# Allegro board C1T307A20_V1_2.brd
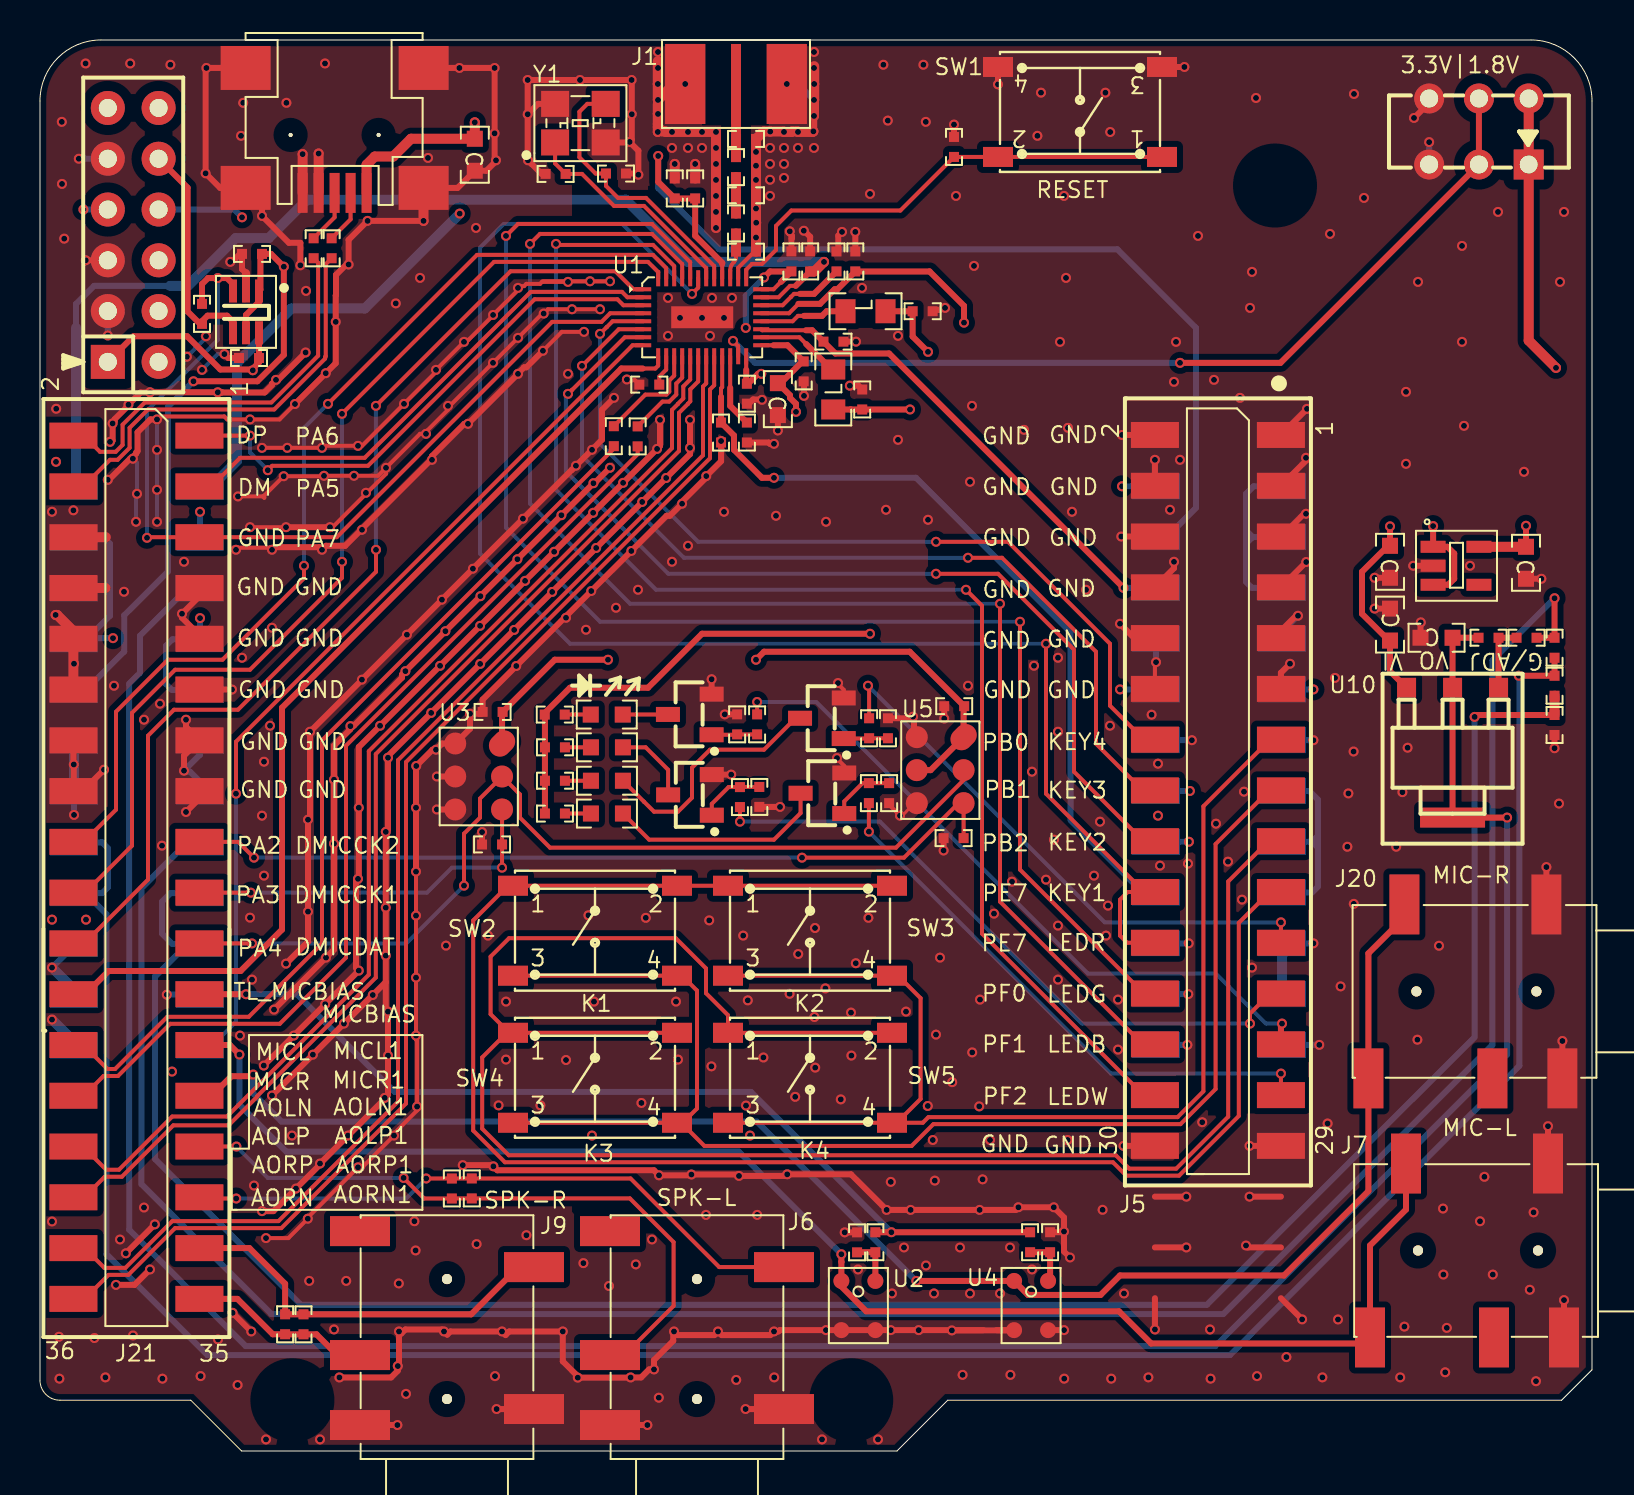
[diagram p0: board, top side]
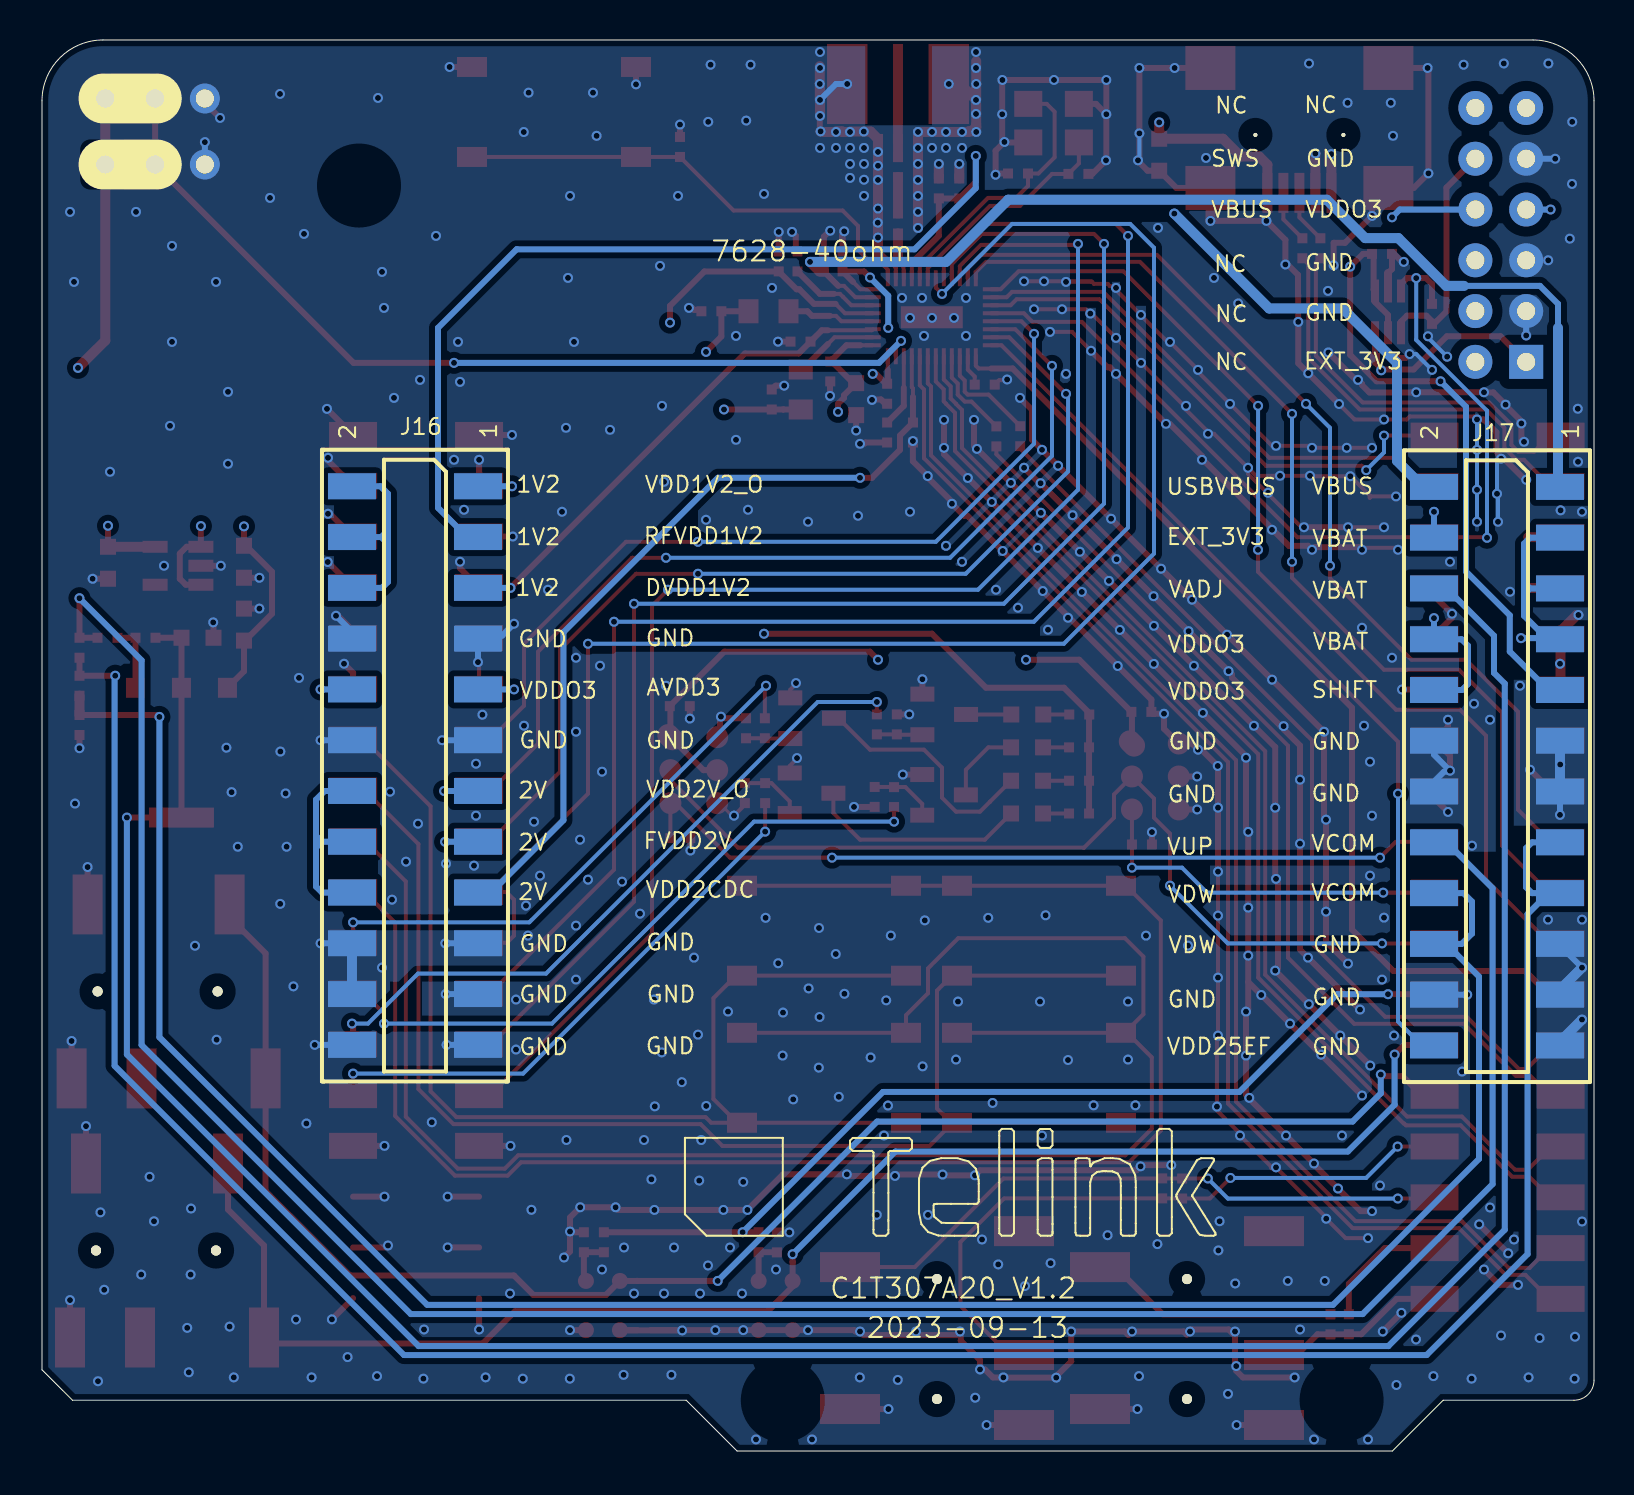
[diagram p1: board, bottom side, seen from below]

Outline 77.6 x 70.58 mm; copper layers: TOP, GND, POWER, BOTTOM. Coordinates in mm from the lower left corner of the outline.
Outline path: 0,67.53 arc(0.89,69.69) 3.05,70.58 74.55,70.58 arc(76.71,69.69) 77.6,67.53 77.6,4.06 76.08,2.54 45.39,2.54 42.85,0 10.08,0 7.54,2.54 1,2.54 arc(0.29,2.83) 0,3.54 0,67.53

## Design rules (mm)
constraint set DEFAULT: min track width 0.15

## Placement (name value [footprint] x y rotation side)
C1  NC  [0402]  28.8 63.9 180 top
C2  NC  [0402]  25.78 63.88 0 top
C3  0.1uF  [0402]  32.76 63.15 90 top
C4  2.2uF  [0402]  31.74 63.15 90 top
C5  NC  [0402]  35.3 59.99 180 top
C6  NC  [0402]  35.3 62.81 180 top
C9  1uF  [0402]  45.7 65.23 90 top
C10  1uF  [0402]  37.57 59.5 90 top
C11  1uF  [0402]  38.51 59.5 90 top
C12  1uF  [0402]  40.77 59.5 90 top
C13  1uF  [0402]  39.83 59.5 90 top
C14  1uF  [0402]  44.13 57.01 0 top
C15  1uF  [0402]  30.46 53.34 180 top
C16  1uF  [0402]  35.34 52.89 270 top
C17  1uF  [0402]  39.67 55.49 0 top
C18  1uF  [0402]  38.19 54 270 top
C19  1uF  [0402]  28.69 50.76 270 top
C20  1uF  [0402]  29.88 50.75 270 top
C21  1uF  [0402]  41.11 52.6 90 top
C22  1uF  [0402]  34.05 50.94 270 top
C23  1uF  [0402]  35.34 50.94 270 top
C25  NC  [0402]  21.59 13.13 90 top
C26  1uF  [0402]  40.85 10.44 90 top
C27  0.1uF  [0402]  45.71 37.26 180 top
C28  NC  [0402]  13.17 6.34 90 top
C29  1uF  [0402]  50.5 10.44 90 top
C30  10uF  [0603C]  21.74 64.84 270 top
C31  0.1uF  [0402]  22.63 36.97 180 top
C33  0.1uF  [0402]  10.6 59.88 180 top
C34  0.1uF  [0402]  10.45 54.67 180 top
C37  10uF  [0603C]  67.5 41.34 90 top
C38  10uF  [0603C]  67.5 44.48 270 top
C39  10uF  [0603C]  74.3 44.43 270 top
C40  10uF  [0603C]  69.83 40.68 180 top
C43  10uF  [0603C]  36.89 52.61 270 top
C44  NC  [0402]  35.3 65.63 180 top
D1  Blue  [0603-LED]  28.34 36.84 0 top
D2  Green  [0603-LED]  28.35 35.2 0 top
D3  White  [0603-LED]  28.35 31.89 0 top
D4  Red  [0603-LED]  28.35 33.53 0 top
J1  RFIN  [SMA-H]  34.8 68.38 270 top
J5  HEADER 15X2  [SMD254M-2X15_RX1_30Y2_40]  58.9 24.15 90 top
J6  AOPHR  [PJ-327]  32.85 -0.4 180 top
J7  AIL1  [PJ-327]  77.9 10.03 270 top
J9  AOPHR  [PJ-327]  20.35 -0.4 180 top
J11  USB_MiniABF  [USB-MINI-F5]  14.73 62.93 180 top
J15  JTAG  [HDR254F-2X6X850]  3.39 67.18 270 top
J16  HEADER 12X2  [SMD254M-2X12_RX1_30Y2_40]  58.95 34.29 90 bottom
J17  HEADER 12X2  [SMD254M-2X12_RX1_30Y2_40]  4.85 34.26 90 bottom
J20  AIL1  [PJ-327]  77.82 22.99 270 top
J21  HEADER 18X2  [SMD254M-2X18_RX1_30Y2_40]  4.82 24.12 90 top
L1  0R  [0402]  34.8 61.4 90 top
L2  2.2uH  [0805L]  41.28 57.01 0 top
L3  2.2uH  [0805L]  39.66 53.1 270 top
L4  0R  [0402]  34.8 64.22 90 top
Q2  C1815  [SOT-23]  39.09 36.65 90 top
Q3  C1815  [SOT-23]  32.49 36.84 90 top
Q4  C1815  [SOT-23]  39.12 32.9 90 top
Q5  C1815  [SOT-23]  32.5 32.82 90 top
R4  1K  [0402]  25.74 36.84 0 top
R5  1K  [0402]  25.75 35.2 0 top
R6  1K  [0402]  25.75 31.89 0 top
R7  1K  [0402]  25.75 33.53 0 top
R8  NC  [0402]  20.59 13.13 90 top
R9  2.2K  [0402]  41.77 10.44 270 top
R10  100K  [0402]  22.6 30.34 0 top
R11  NC  [0402]  12.26 6.34 90 top
R12  2.2K  [0402]  49.5 10.44 270 top
R13  100K  [0402]  45.68 30.66 0 top
R14  33  [0402R]  14.58 60.16 270 top
R15  33  [0402R]  13.68 60.16 270 top
R26  0R  [0402R]  8.1 56.88 270 top
R33  430R  [0402]  74.33 40.68 0 top
R34  1.15K  [0402]  75.73 40.18 270 top
R35  787R  [0402]  75.73 38.28 270 top
R36  464R  [0402]  75.73 36.32 270 top
R37  1K  [0402]  72.43 40.68 180 top
R39  1K  [0402]  35.86 36.35 270 top
R45  1K  [0402]  35 32.71 90 top
R46  1K  [0402]  41.44 32.91 90 top
R47  1K  [0402]  41.46 36.15 270 top
R48  1M  [0402]  34.86 36.35 90 top
R49  1M  [0402]  35.97 32.72 270 top
R50  1M  [0402]  42.46 32.91 270 top
R51  1M  [0402]  42.4 36.15 90 top
S1  SW_SL_DPDT  [SW-TH-6PIN-3_60X9_00-34NP]  71.95 66 0 top
SW1  SW4PIN_4.5x4.5  [SW_6X6_SMD]  52 66.98 180 top
SW2  SW4PIN_4.5x4.5  [SW_6X6_SMD]  27.75 26.03 0 top
SW3  SW4PIN_4.5x4.5  [SW_6X6_SMD]  38.5 26.03 0 top
SW4  SW4PIN_4.5x4.5  [SW_6X6_SMD]  27.75 18.67 0 top
SW5  SW4PIN_4.5x4.5  [SW_6X6_SMD]  38.5 18.67 0 top
U1  TLSR9527B  [QFN_4X6_40PIN_0P4_1P10X3P10]  33.11 56.71 0 top
U2  MWW7037AT2  [GA_BFA423_A83]  40.92 7.28 0 top
U3  SPM0423HM4H-WB  [DMIC_SPM0423HM4H-WB]  21.93 33.74 270 top
U4  MWW7037AT2  [GA_BFA423_A83]  49.55 7.28 0 top
U5  SPM0423HM4H-WB  [DMIC_SPM0423HM4H-WB]  45.01 34.06 270 top
U8  TXS0101  [SC70-6]  10.3 56.98 180 top
U10  LM1117-ADJ  [SOT-223]  70.63 34.68 180 top
U11  CE1132-33M  [SOT-23-5]  70.8 44.28 270 top
Y1  24MHz-12pF-+/-20ppm  [OSCCC250X320X110]  27.02 66.42 90 top

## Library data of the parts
C1 C2 = C1005_NC
C3 C4 C9-C23 C26 C27 C29 C31 C38 C39 = C1005X5R1C104K
C5 C6 C44 = C1608_NC
C25 C28 = C1005X5R1C105K
C30 C37 = C1608X5R0J106M
C33 C34 C40 = C1608X5R1C105M
C43 = C1005X5R1C104K_0
D1-D4 = 0603D_Green
J1 = SMA_JACK_2
J5 = HEADER 15X2: Tolerance: RichardLC
J6 J7 J9 J20 = PJ327_2
J11 = USB_MiniABF_5pin: User Part Number: pn; Tolerance: RichardLC
J15 = HEADER 6X2: User Part Number: pn; Tolerance: RichardLC
J16 J17 = HEADER 12X2: Tolerance: RichardLC
J21 = HEADER 18X2: Tolerance: RichardLC
L1 L4 = MLK1608_000R
L2 L3 = IND
Q2-Q5 = NPN_C1815
R4-R7 = RS0402K102JT
R8-R13 = RS0402K104JT
R14 R15 = RS0603K330JT
R26 = RS0603K102JT
R33-R37 = RS0603K104JT
R39 R45-R51 = RS0402K101JT
S1 = SW_SL_DPDT: User Part Number: pn; Tolerance: RichardLC
SW1-SW5 = SW_6X6_SMD_0
U1 = TLSR9527B
U2 U4 = MULPS4CX-RM5_0
U3 U5 = LD1117/SO_0
U8 = TXS0101
U10 = XC62FP3302_0.3V_SOT-89
U11 = XC6219_6.3V_SOT-23-5
Y1 = CRYSTAL4/SM_0: Tolerance: RichardLC

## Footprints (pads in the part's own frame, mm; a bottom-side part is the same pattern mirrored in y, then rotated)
0402
  rect 0.5x0.5 smd: 1(-0.5,0) 2(0.5,0)
0402R
  rect 0.5x0.5 smd: 1(-0.5,0) 2(0.5,0)
0603-LED
  rect 0.8x0.8 smd: A(-0.8,0) C(0.8,0)
0603C
  rect 0.8x0.8 smd: 1(-0.8,0) 2(0.8,0)
0805L
  rect 1x1.2 smd: 1(-1,0) 2(1,0)
DMIC_SPM0423HM4H-WB
  round 1.1 smd: 1(-1.65,-1.17) 2(0,-1.17) 3(1.65,-1.17) 4(1.65,1.17) 5(0,1.17)
  oval 1.4x1.1 smd rot 135: 6(-1.65,1.17)
GA_BFA423_A83
  round 0.8 smd: 1(-0.85,1.23) 2(-0.85,-1.23) 3(0.85,-1.23) 4(0.85,1.23)
HDR254F-2X6X850
  rect 1.7x1.7 hole 0.9: 1(12.7,0)
  round 1.7 hole 0.9: 2(12.7,2.54) 3(10.16,0) 4(10.16,2.54) 5(7.62,0) 6(7.62,2.54) 7(5.08,0) 8(5.08,2.54) 9(2.54,0) 10(2.54,2.54) 11(0,0) 12(0,2.54)
OSCCC250X320X110
  rect 1.3x1.4 smd: 1(-0.965,1.265) 2(-0.965,-1.265) 3(0.965,-1.265) 4(0.965,1.265)
PJ-327
  round 0.5 hole 1: (0,-3) (0,-9)
  rect 3x1.5 smd: 1(-4.35,-2.5) 2(4.35,-5.2) 3(-4.35,-9.6) 4(4.35,-11.4) 5(4.35,-1.7)
QFN_4X6_40PIN_0P4_1P10X3P10
  rect 0.8x0.2 smd: 1(-2.95,1.4) 2(-2.95,1) 3(-2.95,0.6) 4(-2.95,0.2) 5(-2.95,-0.2) 6(-2.95,-0.6) 7(-2.95,-1) 8(-2.95,-1.4) 21(2.95,-1.4) 22(2.95,-1) 23(2.95,-0.6) 24(2.95,-0.2) 25(2.95,0.2) 26(2.95,0.6) 27(2.95,1) 28(2.95,1.4)
  rect 0.2x0.8 smd: 9(-2.2,-1.95) 10(-1.8,-1.95) 11(-1.4,-1.95) 12(-1,-1.95) 13(-0.6,-1.95) 14(-0.2,-1.95) 15(0.2,-1.95) 16(0.6,-1.95) 17(1,-1.95) 18(1.4,-1.95) 19(1.8,-1.95) 20(2.2,-1.95) 29(2.2,1.95) 30(1.8,1.95) 31(1.4,1.95) 32(1,1.95) 33(0.6,1.95) 34(0.2,1.95) 35(-0.2,1.95) 36(-0.6,1.95) 37(-1,1.95) 38(-1.4,1.95) 39(-1.8,1.95) 40(-2.2,1.95)
  rect 3.1x1.1 smd: 41(0,0)
SC70-6
  rect 0.4x1.15 smd: 1(-0.65,-1.045) 2(0,-1.045) 3(0.65,-1.045) 4(0.65,1.045) 5(0,1.045) 6(-0.65,1.045)
SMA-H
  rect 4x0.5 smd: 1(0,0)
  rect 4x2 smd: 2(0,-2.54) 3(0,2.54) 4(0,-2.54) 5(0,2.54)
SMD254M-2X12_RX1_30Y2_40
  rect 1.3x2.4 smd: 1(13.97,-3.15) 2(13.97,3.15) 3(11.43,-3.15) 4(11.43,3.15) 5(8.89,-3.15) 6(8.89,3.15) 7(6.35,-3.15) 8(6.35,3.15) 9(3.81,-3.15) 10(3.81,3.15) 11(1.27,-3.15) 12(1.27,3.15) 13(-1.27,-3.15) 14(-1.27,3.15) 15(-3.81,-3.15) 16(-3.81,3.15) 17(-6.35,-3.15) 18(-6.35,3.15) 19(-8.89,-3.15) 20(-8.89,3.15) 21(-11.43,-3.15) 22(-11.43,3.15) 23(-13.97,-3.15) 24(-13.97,3.15)
SMD254M-2X15_RX1_30Y2_40
  rect 1.3x2.4 smd: 1(26.67,-3.15) 2(26.67,3.15) 3(24.13,-3.15) 4(24.13,3.15) 5(21.59,-3.15) 6(21.59,3.15) 7(19.05,-3.15) 8(19.05,3.15) 9(16.51,-3.15) 10(16.51,3.15) 11(13.97,-3.15) 12(13.97,3.15) 13(11.43,-3.15) 14(11.43,3.15) 15(8.89,-3.15) 16(8.89,3.15) 17(6.35,-3.15) 18(6.35,3.15) 19(3.81,-3.15) 20(3.81,3.15) 21(1.27,-3.15) 22(1.27,3.15) 23(-1.27,-3.15) 24(-1.27,3.15) 25(-3.81,-3.15) 26(-3.81,3.15) 27(-6.35,-3.15) 28(-6.35,3.15) 29(-8.89,-3.15) 30(-8.89,3.15)
SMD254M-2X18_RX1_30Y2_40
  rect 1.3x2.4 smd: 1(26.67,-3.15) 2(26.67,3.15) 3(24.13,-3.15) 4(24.13,3.15) 5(21.59,-3.15) 6(21.59,3.15) 7(19.05,-3.15) 8(19.05,3.15) 9(16.51,-3.15) 10(16.51,3.15) 11(13.97,-3.15) 12(13.97,3.15) 13(11.43,-3.15) 14(11.43,3.15) 15(8.89,-3.15) 16(8.89,3.15) 17(6.35,-3.15) 18(6.35,3.15) 19(3.81,-3.15) 20(3.81,3.15) 21(1.27,-3.15) 22(1.27,3.15) 23(-1.27,-3.15) 24(-1.27,3.15) 25(-3.81,-3.15) 26(-3.81,3.15) 27(-6.35,-3.15) 28(-6.35,3.15) 29(-8.89,-3.15) 30(-8.89,3.15) 31(-11.43,-3.15) 32(-11.43,3.15) 33(-13.97,-3.15) 34(-13.97,3.15) 35(-16.51,-3.15) 36(-16.51,3.15)
SOT-23
  rect 0.75x1.2 smd: 1(-1.016,-1.092) 2(1.016,-1.092) 3(0,1.092)
SOT-23-5
  rect 0.6x1.25 smd: 1(-0.95,-1.145) 2(0,-1.145) 3(0.95,-1.145) 4(0.95,1.145) 5(-0.95,1.145)
SOT-223
  rect 0.95x1 smd: 1(-2.3,-3.495) 2(0,-3.495) 3(2.3,-3.495)
  rect 3.25x1 smd: 4(0,2.995)
SW-TH-6PIN-3_60X9_00-34NP
  rect 1.499x1.499 hole 0.889: 1(2.489,-1.651)
  round 1.5 hole 0.9: 2(0,-1.651) 3(-2.489,-1.651) 4(-2.489,1.651) 5(0,1.651) 6(2.489,1.651)
SW_6X6_SMD
  rect 1.5x1 smd: 1(-4.1,2.25) 2(4.1,2.25) 3(-4.1,-2.25) 4(4.1,-2.25)
USB-MINI-F5
  round 0.2 hole 0.9 unplated: (-2.2,-2.9) (2.2,-2.9)
  rect 0.5x2 smd: 1(-1.6,0) 2(-0.8,0) 3(0,0) 4(0.8,0) 5(1.6,0)
  rect 2.5x2.2 smd: 6(-4.45,-6.25) 7(4.45,-6.25) 8(-4.45,-0.25) 9(4.45,-0.25)

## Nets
GND: C1.1 C2.1 C3.2 C4.2 C5.1 C6.1 C9.2 C10.2 C11.2 C12.2 C13.2 C14.2 C15.2 C16.2 C17.2 C18.2 C21.2 C22.2 C23.2 C26.2 C27.2 C29.2 C30.2 C31.2 C33.2 C34.2 C37.2 C38.2 C39.2 C40.2 C43.2 C44.1 J1.2 J1.3 J1.4 J1.5 J5.1 J5.2 J5.3 J5.4 J5.5 J5.6 J5.7 J5.8 J5.9 J5.10 J5.11 J5.12 J5.29 J5.30 J6.1 J6.5 J7.1 J7.5 J9.1 J9.5 J11.4 J11.5 J11.6 J11.7 J11.8 J11.9 J15.3 J15.5 J15.9 J16.7 J16.8 J16.11 J16.12 J16.19 J16.20 J16.21 J16.22 J16.23 J16.24 J17.11 J17.12 J17.13 J17.14 J17.19 J17.21 J17.22 J17.23 J20.1 J20.5 J21.6 J21.7 J21.8 J21.9 J21.10 J21.11 J21.12 J21.13 J21.14 J21.15 J21.16 Q2.2(E) Q3.2(E) Q4.2(E) Q5.2(E) R10.1 R13.1 R36.2 R48.2 R49.2 R50.2 R51.2 S1.3 S1.4 SW1.3 SW1.4 U1.30 U1.41 U2.2 U2.3 U3.1 U3.2(SE) U3.3 U4.2 U4.3 U5.1 U5.3 U8.2 U11.2(VSS) Y1.2 Y1.4
VBAT_ADJ: C40.1 J17.6 R37.2 U10.2 U10.4(VOUT#4)
VBUS: C30.1 C37.1 C38.1 J11.1(V_BUS) J15.8 J17.2 U10.3 U11.1 U11.3
VDD25_EF: J17.24 U1.8
AOLN: C25.1 J6.2 J21.29 R8.1
AOLP: C25.2 J6.3 J21.31 R8.2
AORN: C28.1 J9.2 J21.35 R11.1
AORP: C28.2 J9.3 J21.33 R11.2
BEVK_SWS: J15.10 R26.2 U8.4
DM: J21.4 R14.2
DMICCK1: J21.19 R10.2 U3.4
DMICCK2: J21.17 R13.2 U5.4
DMICDAT: J21.21 U3.5 U5.5
DP: J21.2 R15.2
EXT_3V3: C34.1 C39.1 J15.1 J17.4 U8.6(VCCB) U11.5
LED_B: J5.25 R39.1
LED_G: J5.23 R45.1
LED_R: J5.21 R47.1
LED_W: J5.27 R46.1
LEVEL_SHIFT: C27.1 C31.1 C33.1 J17.9 U3.6 U5.2(SE) U5.6 U8.1 U8.5
MICBIAS: J21.23 R9.1 R12.1
MICL: J7.3 J7.4 J21.25 U2.1
MICR: J20.3 J20.4 J21.27 U4.1
TL_AOLN: J21.30 U1.13
TL_AOLP: J21.32 U1.14
TL_AORN: J21.36 U1.16
TL_AORP: J21.34 U1.15
TL_AVDD3: C10.1 J16.9 U1.28
TL_CFG: S1.2 S1.5 U1.19
TL_DVDD1V2: C17.1 J16.5 U1.23
TL_FVDD2V: C12.1 J16.15 U1.25
TL_KEY1: J5.19 SW2.1 SW2.2 SW3.1 SW3.2
TL_KEY2: J5.17 SW4.1 SW4.2 SW5.1 SW5.2
TL_KEY3: J5.15 SW2.3 SW2.4 SW4.3 SW4.4
TL_KEY4: J5.13 SW3.3 SW3.4 SW5.3 SW5.4
TL_MICBIAS: J21.24 U1.9
TL_MICL: C19.2 J21.26
TL_MICR: C20.2 J21.28
TL_PA2: J21.18 U1.39
TL_PA3: J21.20 U1.40
TL_PA4: J21.22 U1.1
TL_PA5_DM: J21.3 U1.2
TL_PA6_DP: J21.1 U1.3
TL_PA7_SWS: J21.5 R26.1 U1.4 U8.3
TL_PB0: J5.14 U1.5
TL_PB1: J5.16 U1.6
TL_PB2: J5.18 U1.7
TL_PE7: J5.20 J5.22 U1.35
TL_PF0: J5.24 U1.36
TL_PF1: J5.26 U1.37
TL_PF2: J5.28 U1.38
TL_RFVDD1V2: C3.1 C4.1 J16.3 U1.32
TL_RST: C9.1 SW1.1 SW1.2 U1.29
TL_VBAT: C18.1 C43.1 J17.3 J17.5 J17.7 R4.1 R5.1 R6.1 R7.1 U1.21
TL_VBUS: C11.1 J17.1 U1.27
TL_VDD1V2_O: C21.1 J16.1 L3.2
TL_VDD2CDC: C22.1 J16.17 U1.17
TL_VDD2V_O: C14.1 J16.13 L2.2
TL_VDDO3: C16.1 J15.7 J16.10 J17.8 J17.10 S1.1 S1.6 U1.20
TL_XC1: C1.2 U1.33 Y1.3
TL_XC2: C2.2 U1.34(XC2) Y1.1
VCOM: J17.15 J17.17 R34.2 R35.1
VDW: J17.18 J17.20 R35.2 R36.1
VUP: J17.16 R33.2 R34.1
N20028206: R33.1 R37.1 U10.1
N20031278: C15.1 U1.10
N20031514: C5.2 L1.1 U1.31
N20035363: C26.1 R9.2 U2.4(VDD)
N20050417: J11.3 R15.1
N20050429: J11.2 R14.1
N20122497: L2.1 U1.24
N20122505: L3.1 U1.22
N20122726: C13.1 U1.26
N20123815: C29.1 R12.2 U4.4(VDD)
N20128470: D4.C(CATHODE) Q2.3
N20128482: Q2.1 R47.2 R51.1
N20128486: D4.A R7.2
N20128502: D1.C(CATHODE) Q3.3
N20128524: Q3.1 R39.2 R48.1
N20128528: D1.A R4.2
N20128530: D3.C(CATHODE) Q4.3
N20128552: Q4.1 R46.2 R50.1
N20128556: D3.A R6.2
N20128560: D2.C(CATHODE) Q5.3
N20128580: Q5.1 R45.2 R49.1
N20128584: D2.A R5.2
N20160217: C23.1 U1.18
N20160455: C20.1 U1.12
N20160512: C19.1 U1.11
N20164995: C44.2 J1.1 L4.2
N20165028: C6.2 L1.2 L4.1
N20174575: J16.2 J16.4 J16.6
N20174708: J16.14 J16.16 J16.18

Pads without a net: J6 4; J7 2; J9 4; J15 2 4 6 11 12; J20 2; U11 4

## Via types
v1: diameter 0.5, hole 0.3, TOP to BOTTOM, 688 vias

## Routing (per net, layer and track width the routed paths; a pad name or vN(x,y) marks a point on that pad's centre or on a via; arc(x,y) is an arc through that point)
GND: length 656.5
  TOP w0.15: v1(43,31.78) 43.13,31.78 43.7,32.4 U5.3 ; 37.57,60.65 37.57,60.75 37.6,60.78
  TOP w0.2: v1(17.3,49.18) 19,50.88 v1(19.3,50.88) 19.4,50.98 19.4,51.08 20.4,52.08 v1(20.4,52.28) 20.49,52.28 22.49,54.28 22.5,54.28 v1(22.65,54.43) v1(23.9,55.68) 25.1,56.88 25.17,56.88 v1(25.18,56.9) 25.4,57.11 v1(26.6,57.11) v1(28,57.11) ; v1(17.3,49.18) 16.9,48.78 v1(15.7,48.78) v1(14.2,48.78) 14.18,48.76 v1(12.19,48.76) 12.19,48.65 12.07,48.65 11.21,47.79 11.21,47.68 11.14,47.75 v1(9.9,47.75) ; v1(17.3,49.18) 17.3,48.88 16.35,47.93 v1(16.3,47.93) 16.3,47.88 14.63,46.21 v1(14.5,46.21) ; 26.47,58.51 v1(27.5,58.51) v1(28.5,58.51) ; 26.47,58.51 25.13,58.51 ; 26.47,58.51 26.44,58.48 v1(26.4,58.48) 25.1,58.48 25,58.38 24.31,58.38 24.2,58.27 23.99,58.27 v1(23.9,58.18) 23.9,58.07 v1(22.65,56.83) 22.65,56.81 21.43,55.58 21.3,55.58 v1(21.2,55.48) v1(19.8,54.08) 19.8,53.98 v1(18.2,52.38) 16.1,50.28 v1(15.9,50.28) 14.2,50.28 v1(14.1,50.18) v1(12.36,50.18) v1(11.1,50.18) ; v1(12.3,46.21) v1(10.5,46.21) ; Q2.2 40.19,38.08 39.9,38.37 v1(39.9,38.41) ; v1(11.6,45.08) 11.5,45.18 9.9,45.18 v1(9.8,45.08) ; v1(39.85,34.66) 39.85,34.63 40.21,34.27 Q4.2 ; 35.8,59.88 C5.1 35.71,59.99 34.91,59.19 U1.30 ; v1(11.3,10.65) 12.42,10.65 v1(13.39,11.62) 13.39,11.68 v1(15.9,14.19) ; v1(29.34,53.6) 29.48,53.6 29.52,53.56 29.74,53.56 C15.2 ; v1(25.15,55.03) 26.09,55.98 v1(27.2,55.98) ; R50.2 42.46,32.32 v1(43,31.78) ; v1(18.8,28.98) v1(18.8,26.78) v1(18.8,23.68) v1(18.8,20.78) 18.8,20.58 18.85,20.53 v1(18.85,17.23) 18.85,17.03 17.7,15.88 v1(17.7,15.78) 16.11,14.19 ; v1(5.85,51.6) 6,51.75 9.21,51.75 9.36,51.6 v1(10.5,51.6) 11.98,51.6 v1(12.75,52.37) ; v1(55.8,39.46) 55.75,39.41 J5.12
  TOP w0.3: v1(45.59,6.03) 48.69,6.03 U4.2 47.83,6.05 ; v1(45.59,6.03) 45.58,6.05 ; v1(45.59,6.03) 45.61,6.05 ; v1(51.2,10.98) 51.16,10.94 C29.2 ; v1(51.2,10.98) 51.2,9.98 v1(51.5,9.68) ; v1(51.2,10.98) 51.2,11.68 v1(50.69,12.19) v1(48.92,12.19) 48.79,12.06 v1(46.98,12.06) v1(43.53,12.06) v1(42.33,12.06) 40.55,13.84 v1(37.36,13.84) 37.28,13.76 v1(34.95,13.76) 34.88,13.83 v1(32.57,13.83) 32.53,13.79 v1(30.95,13.79) 30.7,14.04 22.87,14.04 v1(22.67,14.24) 22.61,14.3 v1(21.14,14.3) 21.09,14.25 ; J5.30 v1(54.18,15.26) ; v1(28.5,49.18) 27.79,48.48 27.74,48.48 v1(27.67,48.41) v1(26.07,46.81) v1(23.87,44.61) v1(22.02,42.76) v1(20.27,41.01) v1(18.27,39.01) 18.1,38.84 18.1,38.69 15.69,36.28 15.54,36.28 v1(15.52,36.26) 15.5,36.24 15.5,36.09 14.7,35.29 v1(14.7,33.58) v1(14.7,30.38) 14.7,25.08 v1(14.3,24.68) v1(11.7,22.08) ; J9.1 v1(22.83,2.1) ; C40.2 69.03,41.44 v1(69.04,41.45) ; v1(9.51,59.48) 9.6,59.48 10,59.88 C33.2 10.1,59.12 10.3,58.92 ; R10.1 v1(22.1,30.96) ; v1(7.3,31.97) 7.97,32.64 J21.15 ; v1(24.38,66.87) 24.38,64.68 24.4,64.66 v1(24.4,64.56) 24.58,64.38 24.58,64.38 25.08,63.88 C2.1 ; v1(24.38,66.87) 24.9,67.39 Y1.4 ; v1(24.38,66.87) v1(24.38,68.58) v1(27,68.58) v1(29.58,68.58) 29.59,68.57 v1(29.59,66.87) 29.59,65.59 v1(29.48,65.48) ; J9.5 v1(17.87,1.3) ; C21.2 40.92,53.29 v1(40.49,53.29) ; v1(9.22,54.87) 9.42,54.67 C34.2 ; C18.2 38.19,53.39 38.2,53.38 v1(38.2,52.78) ; J5.9 62.05,41.03 62.8,41.78 v1(62.9,41.78) ; J20.5 v1(76.12,20.51) ; 17.29,23.46 v1(16.64,22.81) 16.63,22.81 v1(15.2,21.38) v1(13.64,19.83) v1(11.6,17.78) ; 17.29,23.46 17.29,22.09 v1(17.4,21.98) v1(17.4,19.78) 17.4,17.83 v1(17.24,17.66) 17.24,17.62 v1(15.4,15.78) v1(14,14.38) 14,14.33 v1(12.8,13.13) 11.67,12 v1(11.1,12) ; 17.29,23.46 v1(17.29,24.78) v1(17.29,27.18) v1(17.29,30.97) 17.4,31.08 v1(17.4,34.68) 17.4,34.76 v1(19.56,36.92) v1(22.01,39.37) v1(23.71,41.07) v1(25.61,42.97) v1(27.81,45.17) v1(30.11,47.47) v1(31.31,48.67) 32.5,49.86 v1(32.5,50.18) v1(32.5,51.58) ; v1(62.5,39.38) 62.05,38.93 J5.11 ; 45.58,6.05 45.61,6.05 ; 45.58,6.05 v1(43.93,6.05) v1(42.54,6.05) U2.3 U2.2 v1(39.3,6.05) 36.99,6.05 36.92,5.98 v1(36.7,5.98) 36.52,5.8 34.08,5.8 v1(33.9,5.98) 33.72,5.8 31.88,5.8 v1(31.7,5.98) 31.66,5.94 31.66,5.51 30.7,4.55 v1(30.7,4.08) 30.45,4.08 30.05,3.68 v1(29.53,3.68) 29.52,3.67 v1(26.89,3.67) 26.8,3.76 26.8,3.83 26.14,4.49 v1(26.14,5.98) 23.46,5.98 23.28,5.8 v1(23.1,5.98) 20.52,5.98 20.36,5.82 v1(20.2,5.98) 20.1,6.08 18.27,6.08 18.06,5.87 v1(17.95,5.98) 17.95,4.31 v1(17.89,4.25) 17.89,4.02 17.55,3.68 v1(14.97,3.68) ; 35.34,52.39 35.44,52.39 35.66,52.6 36.08,52.6 v1(36.1,52.58) ; C13.2 39.91,60.09 39.91,60.79 v1(40.1,60.98) ; J21.9 7.97,40.81 7.1,41.68 v1(7.1,41.88) 7.97,42.75 J21.7 ; C43.2 v1(36.89,51.05) ; Y1.2 29.45,65.45 v1(29.48,65.48) ; v1(3.8,8.31) 4.73,8.31 v1(5.5,9.08) ; SW1.4 v1(47.9,68.36) ; R13.1 v1(45.18,30.04) ; C10.2 37.57,60.65 37.6,60.68 37.6,60.78 37.49,60.89 v1(37.49,61.01) ; J7.5 v1(76.2,7.55) ; v1(68.7,66.68) 69.46,67.44 S1.4 ; v1(29.48,65.48) 29.92,65.04 v1(29.92,63.84) 29.83,63.84 29.77,63.9 C1.1 ; J5.3 63.3,49.54 v1(63.3,49.68) ; J15.5 v1(2.29,59.56) ; C39.2 v1(75.07,43.63) ; Q3.2 v1(33.58,38.6) ; U3.2 v1(19.84,33.74) ; J5.1 v1(63.35,52.13) ; 34.05,50.45 34.05,49.51 v1(33.31,48.77) 33.31,48.69 32.1,47.48 v1(32.1,47.38) 32.1,47.38 31.5,46.78 31.33,46.78 v1(29.57,45.02) v1(27.56,43.02) 26.3,41.75 v1(26.3,41.68) 26.23,41.68 v1(23.81,39.27) 22.13,37.58 C31.2 22.04,36.88 v1(21.5,36.88) 21.5,36.13 U3.1 20.11,35.39 v1(19.8,35.08) 19.63,35.08 v1(18.81,34.27) 18.8,34.25 v1(18.8,32.18) v1(18.8,28.98) ; 34.05,50.45 C22.2 ; 34.05,50.45 v1(34.05,50.52) ; J7.1 v1(75.4,16.25) ; J5.29 v1(60.48,15.26) ; 45.61,6.05 47.17,6.05 ; J11.7 v1(8.32,69.18) 8.28,69.14 v1(8.28,63.91) 9.01,63.18 J11.9 11.1,62.36 v1(11.1,61.78) 12.45,60.43 13.02,60.43 v1(13.02,59.31) ; J20.1 v1(75.32,29.21) ; J5.5 62.06,45.74 63.2,46.88 v1(63.3,46.88) ; J21.11 v1(9.6,38.09) ; C26.2 v1(40.23,10.94) ; J5.6 v1(54.06,45.74) ; R36.2 v1(75.73,35.15) ; v1(54,41.38) 54.72,40.66 J5.10 ; C9.2 v1(45.7,66.35) ; 62.05,7.64 v1(63.1,6.59) ; C37.2 v1(66.73,42.14) ; v1(3.5,50.48) 3.57,50.48 3.63,50.54 v1(3.63,51.4) 3.73,51.5 3.73,51.61 4.42,52.3 v1(4.42,52.34) 5.03,52.95 5.49,52.95 v1(5.5,52.96) v1(8.89,52.96) 9.09,52.96 9.1,52.95 11.23,52.95 11.6,53.32 11.6,53.38 v1(11.8,53.58) 11.91,53.58 v1(13.28,54.95) ; J5.4 v1(55.75,49.58) ; v1(60.3,10.28) 60.4,10.18 62.05,10.18 ; U11.2 v1(68.66,44.28) ; v1(7.2,34.03) 7.2,34.78 J21.13 7.3,36.22 v1(7.3,36.58) ; v1(5.85,51.6) 5.52,51.6 4.88,50.96 4.88,50.01 4.81,49.94 4.81,49.89 4.64,49.72 v1(4.64,49.64) 4.5,49.64 3.45,48.58 v1(3.39,48.58) ; v1(40.8,55.49) C17.2 ; v1(45.25,57.18) 45.1,57.18 45,57.08 44.7,57.08 C14.2 ; U4.3 v1(51.2,6.05) ; 62.05,12.72 v1(60.48,12.72) ; v1(56.7,44.48) 56.7,44.16 J5.8 ; v1(37,32.22) R49.2 ; v1(12.3,24.38) 13.4,25.48 v1(13.4,26.98) v1(13.4,31.58) 13.5,31.68 v1(13.5,35.98) 16.1,38.58 v1(16.1,38.58) v1(18.35,40.83) v1(20.1,42.58) v1(21.65,44.13) v1(24.15,46.63) 26.59,49.08 v1(26.8,49.28) 27.59,50.08 v1(27.6,50.08) 27.6,50.09 28.1,50.59 28.1,52.08 v1(28.7,52.68) ; J5.7 v1(63.31,44.47) ; J6.5 v1(30.37,1.3) ; v1(38.7,67.58) 38.71,67.57 38.71,66.05 v1(38.67,66.01) ; 55.75,10.18 v1(57.32,10.18) ; C11.2 38.51,60.74 38.21,61.04 v1(38.19,61.04) ; SW1.3 v1(57.22,69.23) ; J21.14 1.67,34.36 v1(1.69,34.34) 1.69,33.03 J21.16 2.13,33.01 v1(3.2,34.08) ; v1(9.63,6.91) v1(10.56,5.98) ; J5.2 v1(54.1,50.82) ; 55.75,12.72 v1(57.32,12.72) ; 31.29,65.98 31.28,65.98 30.89,66.37 ; v1(31,51.58) 31,50.27 v1(30.85,50.13) v1(29.15,48.43) v1(27.66,46.93) v1(25.71,44.98) v1(24.25,43.53) v1(22,41.28) v1(20,39.28) v1(17,36.28) 15.94,35.21 v1(15.94,32.18) 15.94,28.66 v1(15.9,28.62) 15.8,28.52 15.8,24.17 v1(15.94,24.03) v1(14.26,22.35) v1(12.69,20.78) v1(11.19,19.28) ; C12.2 v1(40.77,60.98) ; C27.2 v1(45.21,36.64) ; R48.2 v1(34.24,36.85) ; J11.6 v1(20.97,69.18) v1(22.73,69.18) v1(22.73,65.91) 22.73,64.45 22.32,64.04 C30.2 20.88,63.18 J11.8 19.18,61.53 v1(19.18,61.53) v1(16.38,61.53) 15.43,60.58 v1(15.43,59.35) 15.32,59.35 14.8,58.83 14.8,57.81 14.79,57.8 v1(14.79,56.48) 14.79,54.41 v1(14.29,53.91) v1(12.75,52.37) ; J6.1 v1(35.28,2.1) ; C38.2 v1(66.73,43.68) ; U3.3 v1(19.84,32.09) ; R51.2 43.57,36.65 v1(43.65,36.73) 43.7,36.78 43.7,35.95 43.84,35.81 U5.1 ; Q5.2 v1(34.56,33.84) ; 55.75,7.64 v1(55.75,6.08) ; v1(36.7,50.38) 36.5,50.38 36.44,50.44 C23.2 ; v1(25.15,55.03) 24.32,54.21 24.2,54.21 23.9,53.91 v1(23.9,53.88) v1(21.4,51.38) 21.21,51.38 19.6,49.77 v1(19.6,49.58) 19.55,49.58 16.1,46.13 v1(16.1,46.08) 16.06,46.08 15.26,45.28 14.3,45.28 v1(14.1,45.08) 13.97,45.21 11.73,45.21 v1(11.6,45.08) ; v1(4.29,9.89) v1(5.74,11.34) ; v1(14.5,46.21) v1(12.3,46.21) ; v1(15.9,14.19) 16.11,14.19
  TOP w0.4: 10.3,58.92 U8.2
  TOP w0.5: J21.6 3.29,45.71 ; v1(0.78,41.82) 0.86,41.82 1.67,41.01 J21.10 J21.12 ; v1(30.9,67.58) 30.89,67.59 v1(30.89,68.38) 30.89,69.52 ; v1(30.9,67.58) 31.7,68.38 v1(32.26,68.38) ; v1(30.9,67.58) 30.9,68.37 ; v1(30.9,67.58) v1(30.9,66.88) 30.89,66.89 ; v1(38.7,66.78) v1(38.7,67.58) ; v1(38.7,67.58) 38.71,67.59 v1(38.71,68.38) 38.71,69.27 ; v1(38.7,67.58) 38.7,68.37 ; 30.89,66.89 30.89,67.37 ; 30.89,66.89 30.89,66.23 ; v1(19.18,61.53) 19.18,63.18 J11.8 ; J11.4 v1(13.93,64.9) ; 30.89,66.23 31.11,66.01 31.26,66.01 31.29,65.98 v1(31.6,65.98) v1(32.4,65.98) v1(33.1,65.98) v1(33.8,65.98) v1(33.8,65.18) v1(33.8,64.38) v1(33.8,63.58) v1(33.8,62.78) v1(33.8,61.98) v1(33.8,61.18) ; 30.89,66.23 v1(30.89,65.98) ; J21.8 3.27,43.17 ; C3.2 v1(32.76,64.38) ; J11.5 v1(13.13,64.87) ; v1(38.67,66.01) 38.64,65.98 v1(37.9,65.98) 37.87,66.01 37.61,66.01 37.58,65.98 v1(37.2,65.98) 37.18,66 v1(36.51,66) 36.17,66 C44.1 35.8,64.98 v1(35.8,64.98) v1(35.8,64.29) v1(35.8,63.58) C6.1 v1(35.8,62.15) v1(35.8,60.7) C5.1 ; C4.2 v1(31.74,64.38)
  BOTTOM w0.2: v1(7.34,54.74) 8.3,55.69 v1(8.3,55.76) ; v1(4.64,49.64) 4.85,49.43 v1(4.85,47.88) 4.8,47.83 v1(4.8,46.48) ; v1(22.73,65.91) 22.73,64.63 v1(22.8,64.56) ; v1(5.85,51.6) v1(5.85,50.08) v1(5.85,48.08) v1(5.85,46.48) ; v1(9.22,54.87) 8.89,54.87 v1(8.1,54.08)
  BOTTOM w0.3: v1(38.7,67.58) 37.9,68.38 v1(37.34,68.38) ; J15.3 v1(3.39,55.8) ; J16.20 v1(63.67,25.4) ; v1(0.6,24.18) 1.7,25.28 J17.19 ; J15.9 v1(1.94,64.64) ; J16.19 v1(57.43,25.4) ; v1(54,41.38) 54.6,40.78 55.66,40.78 J16.7 v1(55.8,39.46) ; J16.23 v1(57.37,20.32) ; J17.22 v1(6.34,22.83) ; J17.14 8,33.48 7.5,33.98 7.25,33.98 v1(7.2,34.03) 8,34.83 J17.12 ; J16.8 62.1,40.98 v1(62.9,41.78) ; J17.13 v1(1.7,31.82) ; J16.11 v1(57.59,35.56) ; J16.21 v1(57.42,22.86) ; v1(43,31.78) 43,31.88 ; S1.3 v1(69.46,65.47) ; J16.24 v1(63.96,20.32) ; J16.12 v1(63.67,35.56)
  BOTTOM w0.5: J16.20 J16.22 ; v1(0.6,24.18) 1.7,23.08 J17.21 ; J17.23 1.7,20.48 v1(0.6,21.58) ; J17.13 J17.11
  vias: v1(0.6,46.98) v1(0.6,26.58) v1(0.6,11.48) v1(0.81,52.13) v1(0.8,49.48) v1(0.95,5.71) v1(0.97,3.62) v1(1.09,66.48) v1(1.1,63.38) v1(1.21,60.64) v1(1.67,47.05) v1(1.7,39.38) v1(2.28,69.41) v1(2.3,26.58) v1(2.72,5.65) v1(3.27,3.68) v1(3.7,38.28) v1(4,10.58) v1(4.2,42.98) v1(4.51,69.41) v1(4.65,5.78) v1(5.2,36.58) v1(5.2,12.18) v1(6,37.38) v1(6.1,30.28) v1(6.12,3.62) v1(6.52,69.34) v1(6.6,18.98) v1(7.2,44.48) v1(8.03,3.75) v1(8.9,5.58) v1(9.88,3.3) v1(10,20.78) v1(10.05,65.79) v1(10.1,39.68) v1(10.16,67.44) v1(10.5,26.68) v1(10.6,23.58) v1(10.7,13.28) v1(11.1,31.78) v1(11.2,34.48) v1(11.2,28.78) v1(11.3,0.58) v1(11.5,36.28) v1(11.6,41.18) v1(12.32,67.44) v1(12.6,15.78) v1(13.3,58.03) v1(13.46,8.51) v1(14,0.58) v1(14.25,69.41) v1(14.7,6.08) v1(15.31,8.51) v1(17.79,57.4) v1(17.94,8.38) v1(18.3,2.86) v1(18.72,11.49) v1(18.78,10.03) v1(19,58.68) v1(19.4,64.68) v1(20.3,25.28) v1(21.8,61.18) v1(21.83,10.35) v1(22.4,25.78) v1(22.75,3.75) v1(22.93,17.29) v1(23.3,22.48) v1(23.3,19.58) v1(24.32,10.8) v1(25.02,17.29) v1(26.3,19.56) v1(26.4,53.88) v1(27.17,9.4) v1(27.3,41.08) v1(27.42,26.8) v1(27.6,15.78) v1(27.7,22.48) v1(28.45,8.25) v1(28.8,42.18) v1(29.79,9.33) v1(29.9,43.08) v1(30.07,17.41) v1(30.29,26.67) v1(30.6,10.58) v1(30.9,69.98) v1(30.9,69.18) v1(30.94,2.67) v1(31.4,57.68) v1(31.4,55.78) v1(31.6,65.18) v1(31.6,44.48) v1(31.8,22.48) v1(31.9,19.58) v1(32,56.68) v1(32.4,65.18) v1(32.4,45.28) v1(33.1,65.18) v1(33.1,56.68) v1(33.3,11.81) v1(33.5,55.78) v1(33.46,26.54) v1(33.6,57.68) v1(33.57,19.24) v1(34.2,56.68) v1(34.2,46.98) v1(34.6,57.68) v1(34.81,3.56) v1(35.16,25.78) v1(35.3,17.28) v1(35.39,22.54) v1(35.5,15.78) v1(35.81,61.44) v1(35.86,11.81) v1(36.17,19.68) v1(36.5,65.18) v1(36.5,64.38) v1(36.5,63.59) v1(36.5,62.78) v1(36.71,3.68) v1(36.8,46.78) v1(37.2,65.18) v1(37.2,64.38) v1(37.2,63.68) v1(37.48,22.87) v1(37.76,17.72) v1(37.9,65.18) v1(37.91,24.86) v1(38.7,69.98) v1(38.7,69.18) v1(38.7,65.18) v1(38.72,21.71) v1(38.75,26.16) v1(38.76,19.18) v1(39.1,0.58) v1(39.3,46.48) v1(39.27,23.14) v1(40.04,17.59) v1(40.55,21.93) v1(40.57,19.78) v1(40.79,24.4) v1(40.9,9.08) v1(41.1,58.18) v1(41.42,26.67) v1(41.5,62.88) v1(41.9,0.58) v1(42.17,69.34) v1(42.3,47.08) v1(42.39,66.55) v1(42.54,13.46) v1(42.6,7.88) v1(42.9,55.78) v1(42.9,50.58) v1(43.2,10.18) v1(43.3,21.98) v1(44.17,69.34) v1(44.29,66.48) v1(44.3,9.28) v1(44.4,46.58) v1(44.39,17.26) v1(44.64,15.56) v1(44.74,13.53) v1(44.7,7.88) v1(44.8,20.83) v1(45,24.68) v1(45.61,18.45) v1(45.8,62.78) v1(46,10.18) v1(46.13,3.81) v1(46.4,38.28) v1(46.5,48.48) v1(46.5,7.88) v1(46.6,52.28) v1(46.61,19.94) v1(46.7,59.28) v1(47,22.58) v1(46.96,17.24) v1(47.13,13.59) v1(47.5,15.56) v1(47.7,26.88) v1(48,7.88) v1(48.5,10.18) v1(48.52,3.81) v1(48.6,28.48) v1(49.2,51.08) v1(49.6,33.98) v1(49.6,9.08) v1(49.7,39.28) v1(49.87,65.79) v1(50.05,67.94) v1(50.3,28.58) v1(50.7,30.58) v1(50.9,39.68) v1(50.9,35.98) v1(50.9,26.28) v1(50.9,23.58) v1(51,55.48) v1(51.2,62.78) v1(51.21,3.62) v1(51.3,58.68) v1(51.4,51.18) v1(51.38,15.56) v1(51.6,46.98) v1(52.3,43.08) v1(52.7,28.78) v1(53,31.48) v1(53.13,12.06) v1(53.27,67.94) v1(53.3,25.78) v1(53.4,27.28) v1(53.51,65.98) v1(53.5,36.28) v1(53.56,3.62) v1(53.9,22.58) v1(53.9,20.08) v1(54.2,7.88) v1(55.42,3.68) v1(55.58,36.83) v1(55.9,34.38) v1(55.9,31.78) v1(56,29.28) v1(56.5,47.08) v1(56.7,53.48) v1(56.8,55.48) v1(57,49.58) v1(57.4,29.38) v1(57.9,60.78) v1(58.11,16.45) v1(58.5,6.08) v1(58.53,3.62) v1(58.7,53.58) v1(58.8,31.38) v1(59.4,29.48) v1(60,52.68) v1(60.1,27.58) v1(60.2,32.98) v1(60.5,57.18) v1(60.6,58.98) v1(60.6,24.18) v1(60.8,67.68) v1(60.85,3.75) v1(62.32,4.7) v1(64.12,3.68) v1(64.38,16.38) v1(64.5,60.88) v1(64.75,38.67) v1(64.9,6.58) v1(65.03,23.24) v1(65.42,32.89) v1(65.37,30.23) v1(65.7,67.88) v1(65.68,34.99) v1(65.69,27.37) v1(66.2,62.68) v1(67.81,30.23) v1(68.01,3.68) v1(68.12,32.96) v1(68.22,6.22) v1(68.3,52.98) v1(68.3,49.38) v1(68.38,35.18) v1(68.9,58.48) v1(68.87,20.57) v1(69.95,25.27) v1(70.15,12.13) v1(70.17,8.83) v1(70.34,6.16) v1(70.26,3.94) v1(71.1,60.28) v1(71.1,55.48) v1(71.2,51.28) v1(71.5,44.28) v1(72,11.49) v1(72.22,13.72) v1(72.64,8.83) v1(72.9,61.98) v1(74.2,48.98) v1(74.49,8.06) v1(74.68,11.94) v1(74.8,3.49) v1(76,58.48) v1(75.95,32.38) v1(76.2,61.98)
VBAT_ADJ: length 136.1
  TOP w0.3: v1(73.36,31.68) 70.63,31.68 U10.2 C40.1 R37.2
  BOTTOM w0.3: J17.6 7.37,43.15 5,40.78 5,38.92 4.46,38.38 4.46,11.07 10.28,5.25 58.77,5.25 73.36,19.84 v1(73.36,31.68)
VBUS: length 48.4
  TOP w0.3: U11.3 70.41,43.33 70.71,43.63 70.71,44.89 70.37,45.23 U11.1 v1(69.66,46.27) ; v1(67.5,46.25) C38.1 67.4,45.28 66.1,43.98 66.1,41.88 67.44,40.54 C37.1 67.5,39 U10.3
  TOP w0.5: v1(21.74,66.46) C30.1 18.55,65.64 17.66,64.75 16.74,64.75 16.33,64.34 J11.1
  BOTTOM w0.3: v1(10.1,61.71) 9.71,62.1 J15.8
  BOTTOM w0.5: v1(20.98,61.89) 16.24,57.15 12.57,57.15 9.85,54.43 9.85,49.53 8.55,48.23 J17.2
VDD25_EF: length 44.9
  TOP w0.2: v1(9.8,32.88) 9.8,35.48 29.63,55.31 U1.8
  BOTTOM w0.2: J17.24 8.61,20.29 9.8,21.48 v1(9.8,32.88)
AOLN: length 33.1
  TOP w0.2: J6.2 29.22,4.8 31.68,7.26 31.68,10.45 29.5,12.63 C25.1 20.6,12.63 R8.1 19.21,12.63 v1(18.18,13.66) ; v1(9.82,15.23) J21.29
  BOTTOM w0.2: v1(9.82,15.23) 11.39,13.66 v1(18.18,13.66)
AOLP: length 31.5
  TOP w0.2: v1(9.81,12.63) 8.03,12.63 J21.31 ; v1(19.31,13.63) R8.2 20.6,13.63 C25.2 29.53,13.63 33.96,9.2 J6.3
  BOTTOM w0.2: v1(19.31,13.63) 18.31,12.63 v1(9.81,12.63)
AORN: length 9.2
  TOP w0.3: J9.2 14.86,4.8 13.82,5.84 C28.1 12.26,5.84 R11.1 11.64,5.84 9.87,7.61 J21.35
AORP: length 20
  TOP w0.3: J9.3 23.92,9.2 21.56,6.84 C28.2 12.26,6.84 R11.2 12.26,8.36 10.47,10.15 J21.33
BEVK_SWS: length 11.7
  TOP w0.3: U8.4 9.65,56.49 9.35,56.79 8.38,56.79 8.1,56.51 R26.2 8,56.38 7.38,57 7.38,63.19 J15.10
DM: length 21
  TOP w0.2: R14.2 14.29,59.37 14.29,54.76 14.26,54.73 14.26,54.64 11.72,52.1 5.4,52.1 4.48,51.18 4.48,50.18 3.88,49.58 3.5,49.58 2.17,48.25 J21.4
DMICCK1: length 18.6
  TOP w0.2: U3.4 R10.2 v1(23.1,29.18) ; J21.19 v1(10.54,27.93)
  BOTTOM w0.2: v1(10.54,27.93) 19.35,27.93 20.6,29.18 v1(23.1,29.18)
DMICCK2: length 41.4
  TOP w0.2: v1(10.7,29.68) 9.91,30.47 J21.17 ; R13.2 U5.4 45.93,32.41 43.2,29.68 v1(38.1,29.68)
  BOTTOM w0.2: v1(10.7,29.68) v1(38.1,29.68)
DMICDAT: length 47.8
  TOP w0.2: v1(21.2,28.28) 21.2,30.88 22,31.68 22,32.64 U3.5 24,32.84 24,31.68 25.5,30.18 42.8,30.18 46.18,33.56 U5.5 ; J21.21 v1(10.6,25.39)
  BOTTOM w0.2: v1(21.2,28.28) 18.31,25.39 v1(10.6,25.39)
DP: length 20.1
  TOP w0.2: J21.2 2.19,50.79 3,49.98 3.79,49.98 4.13,50.33 4.13,51.34 5.24,52.45 11.57,52.45 13.91,54.79 13.91,59.44 R15.2
EXT_3V3: length 15.2
  TOP w0.3: U8.6 C34.1 10.95,54.45 10.64,54.14 v1(10.64,54.06) 10.6,54.1 9.02,54.1 7.36,55.76 4.67,55.76 J15.1 ; C39.1 v1(74.3,46.28)
  TOP w0.5: U11.5 C39.1
  BOTTOM w0.3: v1(8,46.98) J17.4
LED_B: length 34.6
  TOP w0.2: v1(35.86,37.47) R39.1
  TOP w0.3: v1(62.1,21.38) 62.05,21.33 J5.25
  BOTTOM w0.2: v1(62.1,21.38) 61.3,21.38 58.8,23.88 52.4,23.88 38.81,37.47 v1(35.86,37.47)
LED_G: length 32.9
  TOP w0.2: J5.23 61.5,22.88 60.5,21.88 v1(60.5,21.38) ; R45.1 v1(35,31.48)
  BOTTOM w0.2: v1(35,31.48) 42,31.48 52.1,21.38 v1(60.5,21.38)
LED_R: length 28.2
  TOP w0.2: R47.1 41.46,38.22 v1(41.4,38.28) ; J5.21 v1(62.05,26.44)
  BOTTOM w0.2: v1(62.05,26.44) 53.24,26.44 v1(41.4,38.28)
LED_W: length 28.1
  TOP w0.2: v1(62.05,18.88) J5.27 ; R46.1 v1(41.44,30.98)
  BOTTOM w0.2: v1(62.05,18.88) 53.55,18.88 v1(41.44,30.98)
LEVEL_SHIFT: length 57.6
  TOP w0.3: U8.5 10.3,56.83 10.95,57.48 U8.1 11.02,58.09 11.02,59.8 C33.1 11.55,59.88 12.19,59.24 ; v1(35.8,39.58) 36.2,39.98 43.49,39.98 C27.1 46.18,37.23 U5.6 44.53,34.06 U5.2 ; 12.19,59.24 v1(12.19,59.24) ; 12.19,59.24 12.19,54.83 10.87,53.51 v1(7.67,53.51) ; U3.6 23.1,36.94 C31.1 25.74,39.58 v1(28.4,39.58)
  BOTTOM w0.3: J17.9 2.29,38.07 4.21,39.99 4.21,41.8 6.4,43.99 6.4,52.23 v1(7.67,53.51)
MICBIAS: length 47.3
  TOP w0.3: R9.1 v1(42.57,10.94) R12.1 ; J21.23 v1(10.3,22.85)
  BOTTOM w0.3: v1(10.3,22.85) 12.84,22.85 17.73,17.96 35.55,17.96 v1(42.57,10.94)
MICL: length 76.7
  TOP w0.3: v1(40.07,9.84) 40.07,9.46 40.07,9.46 U2.1 40.07,8.23 41.31,6.99 53.95,6.99 55.56,5.38 66.2,5.38 J7.4 66.5,10.28 68.3,12.08 J7.3 ; J21.25 9.49,20.31 v1(9.97,19.83)
  BOTTOM w0.3: v1(40.07,9.84) 34.93,14.98 12.31,14.98 9.97,17.32 v1(9.97,19.83)
MICR: length 81.2
  TOP w0.3: J21.27 8.59,17.77 9.57,18.75 10.58,18.75 v1(10.66,18.83) ; J20.3 68.22,26.69 66.42,24.89 J20.4 66.42,13 62.2,8.78 54,8.78 53.03,7.81 49.4,7.81 U4.1 47.84,8.51 47.84,8.51 v1(43.81,8.51)
  BOTTOM w0.3: v1(43.81,8.51) 35.84,16.48 12.07,16.48 10.66,17.89 v1(10.66,18.83)
TL_AOLN: length 56.9
  TOP w0.2: J21.30 2.15,15.23 3.31,14.07 3.95,14.07 6.61,16.73 9.35,16.73 16.44,23.82 16.44,35.01 31.6,50.17 31.6,52.08 31.9,52.38 31.9,52.38 32.16,52.65 32.16,53.25 32.51,53.59 U1.13
TL_AOLP: length 57.4
  TOP w0.2: J21.32 2.21,12.69 3.24,13.72 4.09,13.72 6.67,16.29 9.4,16.29 9.49,16.38 9.52,16.38 10.85,17.71 10.85,17.74 16.79,23.68 16.79,34.86 31.95,50.02 31.95,51.93 32.4,52.38 32.4,52.39 32.51,52.5 32.51,53.1 32.91,53.5 U1.14
TL_AORN: length 64.4
  TOP w0.2: J21.36 2.23,7.61 3.43,8.81 4.42,8.81 6.75,11.15 12.07,11.15 18.3,17.38 18.3,34.46 33.5,49.66 33.5,53.1 33.71,53.31 U1.16
TL_AORP: length 63.8
  TOP w0.2: J21.34 2.23,10.15 3.22,9.16 4.27,9.16 6.61,11.5 11.93,11.5 17.9,17.48 17.9,34.56 33.15,49.81 33.15,53.24 33.31,53.4 33.31,54.76
TL_AVDD3: length 8.1
  TOP w0.2: 37.05,58.48 36.68,58.11 U1.28
  TOP w0.3: 37.05,58.48 C10.1 36.5,59 v1(36.2,58.7)
  BOTTOM w0.3: v1(36.2,58.7) 35.29,57.79 v1(35.29,56.18) ; J16.9 v1(54,38.1)
TL_CFG: length 46
  TOP w0.2: U1.19 34.91,55.27 v1(34.65,55.53)
  TOP w0.3: v1(57,54.43) 62.02,54.43 S1.2 S1.5
  BOTTOM w0.3: v1(57,54.43) 35.75,54.43 v1(34.65,55.53)
TL_DVDD1V2: length 25.1
  TOP w0.2: U1.23 36.11,56.06 38.3,56.06
  TOP w0.3: v1(54.18,43.18) 42.45,54.9 39.77,54.9 C17.1 38.6,56.06 38.3,56.06
  BOTTOM w0.3: v1(54.18,43.18) J16.5
TL_FVDD2V: length 14.2
  TOP w0.2: U1.25 37.45,56.91 37.92,57.38
  TOP w0.3: v1(46.2,56.44) 46.2,57.28 44.48,59 C12.1 39.87,58.11 39.73,58.11 39,57.38 37.92,57.38
  BOTTOM w0.3: J16.15 v1(57.45,30.48)
TL_KEY1: length 85
  TOP w0.2: J5.19 61.48,27.96 59.94,26.42 59.94,16.76 56.96,13.77 54.32,13.77 53.65,14.44 23.25,14.44 21.66,16.03 21.66,26.54 23.4,28.28 SW2.1 SW2.2 SW3.1 SW3.2
TL_KEY2: length 96.1
  TOP w0.2: 23.46,20.92 22.53,21.85 22.53,24.73 23.45,25.65 31.79,25.65 33.3,24.14 33.3,22.9 34.4,21.8 SW5.1 SW5.2 ; 23.46,20.92 23.34,20.92 22.11,19.69 22.11,16.12 23.44,14.79 53.79,14.79 54.46,14.12 56.81,14.12 59.41,16.72 59.41,28.49 61.42,30.5 J5.17 ; 23.46,20.92 SW4.1 SW4.2
TL_KEY3: length 69.9
  TOP w0.2: SW4.3 SW4.4 32.06,16.42 ; 32.06,16.42 32.14,16.42 32.85,17.13 32.85,23.03 32.1,23.78 SW2.4 SW2.3 ; 32.06,16.42 33.22,15.26 43.58,15.26 44.67,16.35 57.02,16.35 58.78,18.1 58.78,30.36 61.46,33.04 J5.15
TL_KEY4: length 60.8
  TOP w0.2: 42.84,16.42 SW5.4 SW5.3 ; 42.84,16.42 44.14,16.42 44.42,16.7 56.88,16.7 58.17,17.99 58.17,32.25 61.5,35.58 J5.13 ; 42.84,16.42 44.03,17.61 44.03,22.65 42.9,23.78 SW3.4 SW3.3
TL_MICBIAS: length 49.2
  TOP w0.2: 30.13,54.15 30.77,54.15 30.91,54.29 30.91,54.76
  TOP w0.3: J21.24 2.27,22.85 3.43,24.01 10.03,24.01 12.1,26.08 12.1,37.18 29.07,54.15 30.13,54.15
TL_MICL: length 46.4
  TOP w0.2: J21.26 2.17,20.31 3.37,19.11 3.75,19.11 6.37,21.72 10.44,21.72 14.1,25.38 14.1,35.55 28.69,50.14 C19.2
TL_MICR: length 48.1
  TOP w0.2: J21.28 2.19,17.77 3.18,18.76 3.9,18.76 6.51,21.37 11.99,21.37 15.3,24.68 15.3,35.28 29.88,49.86 C20.2
TL_PA2: length 49.9
  TOP w0.2: v1(14.4,52.38) 21.85,59.83 30.65,59.83 31.31,59.17 U1.39 ; J21.18 2.19,30.47 3.8,32.08 3.8,36.98 6.4,39.58 9.12,39.58 13.2,43.66 v1(13.2,44.28)
  BOTTOM w0.2: v1(13.2,44.28) 13.2,51.18 v1(14.4,52.38)
TL_PA3: length 51.5
  TOP w0.2: J21.20 2.25,27.93 4.6,30.28 4.6,36.92 6.76,39.08 10.5,39.08 15.1,43.68 v1(15.1,44.48) ; v1(15.1,51.88) 22.7,59.48 30.4,59.48 30.91,58.97 30.91,58.66
  BOTTOM w0.2: v1(15.1,44.48) v1(15.1,51.88)
TL_PA4: length 51.9
  TOP w0.2: v1(16.8,45.08) 16.8,43.98 9.9,37.08 6.7,37.08 5.4,35.78 5.4,28.58 2.21,25.39 J21.22 ; v1(16.8,52.28) 23.53,59.01 28.77,59.01 29.67,58.11 U1.1
  BOTTOM w0.2: v1(16.8,52.28) 16.8,45.08 v1(16.8,45.08)
TL_PA5_DM: length 26.3
  TOP w0.2: J21.3 8.57,48.25 10,49.68 16.23,49.68 24.53,57.98 29.1,57.98 29.37,57.71 U1.2
TL_PA6_DP: length 27.1
  TOP w0.2: U1.3 29.17,57.31 28.87,57.61 24.73,57.61 16.4,49.28 11.61,49.28 v1(11.39,49.06) ; v1(10.5,50.79) J21.1
  BOTTOM w0.2: v1(10.5,50.79) 10.5,49.95 v1(11.39,49.06)
TL_PA7_SWS: length 47.1
  TOP w0.2: U1.4 28.51,56.91 28.08,56.48 25.61,56.48 14.84,45.71 J21.5 5.38,45.71 v1(5.35,45.68)
  TOP w0.3: R26.1 8.1,58.37 8.4,58.67 v1(8.89,58.67) 9.35,58.67 9.65,58.37 U8.3
  BOTTOM w0.2: v1(8.89,58.67) 8.89,55.58 5.35,52.04 v1(5.35,45.68)
TL_PB0: length 43.6
  TOP w0.2: J5.14 55.2,35.58 53.5,37.28 53.5,40.38 48.4,45.48 v1(44.8,45.48) ; U1.5 28.63,56.51 28.33,56.21 28.33,56.21 v1(28,55.88)
  BOTTOM w0.2: v1(44.8,45.48) 32.91,45.48 28,50.39 v1(28,55.88)
TL_PB1: length 46.6
  TOP w0.2: v1(27.1,54.28) 27.1,54.28 28.94,56.11 U1.6 ; v1(46.4,44.68) 48.1,44.68 52.8,39.98 52.8,35.38 55.14,33.04 J5.16
  BOTTOM w0.2: v1(27.1,54.28) 27.1,49.77 32.2,44.68 v1(46.4,44.68)
TL_PB2: length 49.5
  TOP w0.2: J5.18 55.18,30.5 51.7,33.98 51.7,40.08 47.9,43.88 v1(44.8,43.88) ; v1(26.4,52.88) 26.6,53.08 26.61,53.08 29.24,55.71 U1.7
  BOTTOM w0.2: v1(26.4,52.88) 26.3,52.78 26.3,49 31.41,43.88 v1(44.8,43.88)
TL_PE7: length 79
  TOP w0.2: J5.22 54.36,25.42 54,25.78 54,27.58 54.38,27.96 55.22,27.96 ; 55.22,27.96 J5.20 ; 55.22,27.96 50.3,32.88 v1(50.3,40.38) ; v1(32.6,57.88) 32.91,58.19 U1.35
  BOTTOM w0.2: v1(50.3,40.38) 26.51,40.38 22,44.89 22,60.19 23.19,61.38 29.1,61.38 v1(32.6,57.88)
TL_PF0: length 75
  TOP w0.2: v1(23.3,60.78) 23.9,61.38 30.6,61.38 32.51,59.47 U1.36 ; v1(49,41.48) 49,29.08 55.2,22.88 J5.24
  BOTTOM w0.2: v1(23.3,60.78) 23.3,46.19 28.01,41.48 v1(49,41.48)
TL_PF1: length 73.3
  TOP w0.2: v1(24.5,60.38) 25,60.88 30.6,60.88 32.11,59.37 U1.37 ; v1(48,42.38) 48,27.48 55.14,20.34 J5.26
  BOTTOM w0.2: v1(48,42.38) 29.51,42.38 24.5,47.39 v1(24.5,60.38)
TL_PF2: length 71.4
  TOP w0.2: 31.71,58.66 31.71,59.27 30.65,60.33 25.85,60.33 v1(25.8,60.38) ; J5.28 55.18,17.8 47.1,25.88 47.1,42.28 v1(46.3,43.08)
  BOTTOM w0.2: v1(25.8,60.38) 25.8,48.08 30.8,43.08 v1(46.3,43.08)
TL_RFVDD1V2: length 51
  TOP w0.2: 34.11,59.37 U1.32
  TOP w0.3: v1(30.91,64.78) 30.91,63.48 C4.1 C3.1 32.76,60.79 34.11,59.44 34.11,59.37
  BOTTOM w0.3: J16.3 56.34,45.72 57.8,47.18 57.8,56.18 53.87,60.11 33.97,60.11 30.91,63.17 v1(30.91,64.78)
TL_RST: length 24.3
  TOP w0.2: 35.31,58.66 35.31,59.09 35.6,59.38 36.1,59.38 36.8,60.08 36.8,61.28 37.57,62.05 43.02,62.05 C9.1 SW1.2 SW1.1
TL_VBAT: length 41
  TOP w0.2: 36.68,55.31 U1.21
  TOP w0.3: R6.1 R7.1 R5.1 25.25,36.83 R4.1 25.24,36.92 26.5,38.18 30.4,38.18 33.1,40.88 v1(41.5,40.88) ; 36.68,55.31 37.38,55.31 C18.1 38.12,54.5 37.03,53.41 C43.1 37.5,52.81 37.5,52.68 37.8,52.38 v1(37.8,51.98)
  BOTTOM w0.3: 1.81,40.61 2.33,40.61 3.5,41.78 3.5,42.85 ; 1.81,40.61 1.86,40.66 v1(3.65,40.66) ; 1.81,40.61 J17.7 ; 3.2,43.15 J17.5 ; 3.2,43.15 3.5,42.85 ; 3.2,43.15 3.5,43.45 ; 3.5,42.85 3.5,43.45 ; 3.5,43.45 3.5,45.39 3.2,45.69 J17.3
TL_VBUS: length 53.9
  TOP w0.2: U1.27 36.93,57.71 37.5,58.28 37.78,58.28
  TOP w0.3: 37.78,58.28 C11.1
  TOP w0.5: v1(39.2,59.48) 38.72,59 C11.1
  BOTTOM w0.3: 6.5,58.28 2.7,58.28 1.8,57.38 1.8,56.18
  BOTTOM w0.5: 1.8,56.18 1.8,48.32 J17.1 ; v1(39.2,59.48) 32.4,59.48 29.29,62.59 13.36,62.59 11.44,60.67 9.78,60.67 7.39,58.28 6.5,58.28
TL_VDD1V2_O: length 5.5
  TOP w0.3: L3.2 40.53,52.1 40.53,52.1 C21.1 v1(43.5,52.1)
  BOTTOM w0.3: J16.1 v1(54.1,48.26)
TL_VDD2CDC: length 40.8
  TOP w0.2: U1.17 34.11,53.21 34.05,53.16 34.05,52.73
  TOP w0.3: 34.05,52.73 C22.1 34.7,50.8 34.7,50.08 36.1,48.68 v1(36.7,48.68)
  BOTTOM w0.3: J16.17 55.14,27.94 51.53,31.55 51.53,40.95 43.8,48.68 v1(36.7,48.68)
TL_VDD2V_O: length 5.4
  TOP w0.3: L2.2 C14.1 43.63,55.75 v1(44.4,54.98)
  BOTTOM w0.3: J16.13 v1(57.49,33.02)
TL_VDDO3: length 25.8
  TOP w0.2: 35.31,54.08 35.31,54.76
  TOP w0.3: 35.31,54.08 35.31,53.42 C16.1 35.41,53.39 35.9,53.88 v1(36.06,53.88)
  TOP w0.5: v1(75.8,54.18) 74.44,55.55 S1.1 S1.6
  BOTTOM w0.3: J16.10 v1(63.67,38.1) ; J15.7 v1(2.17,62.1) ; v1(8,41.66) J17.8 6.63,40.61 6.3,40.28 6.3,38.37 6.6,38.07 J17.10
TL_XC1: length 13.7
  TOP w0.2: Y1.3 27.36,67.39 26.97,66.99 26.97,64.71 27.78,63.9 C1.2 28.3,63.28 28.9,62.68 30.3,62.68 33.71,59.27 U1.33
TL_XC2: length 11.3
  TOP w0.2: Y1.1 25.75,64.41 C2.2 27.1,63.88 28.7,62.28 30.2,62.28 33.31,59.17 33.31,58.66
VCOM: length 125
  TOP w0.3: v1(73.94,38.78) R35.1 R34.2
  BOTTOM w0.3: J17.15 3.1,30.45 3.4,30.15 3.4,28.21 3.1,27.91 2.27,27.91 ; v1(73.94,38.78) 73.97,38.75 73.97,19.27 59.5,4.8 8.37,4.8 3.32,9.85 3.32,26.86 2.27,27.91 ; J17.17 2.27,27.91
VDW: length 112.7
  TOP w0.3: R36.1 71.83,36.82 v1(71.73,36.72)
  TOP w0.5: R35.2 R36.1
  BOTTOM w0.3: 7.08,25.37 6.61,25.37 6.1,25.88 6.1,27.48 6.53,27.91 J17.18 ; 7.08,25.37 7.08,25.06 5.75,23.73 5.75,14.61 13.05,7.31 58.34,7.31 71.73,20.7 v1(71.73,36.72) ; 7.08,25.37 J17.20
VUP: length 121
  TOP w0.3: R33.2 R34.1 v1(75.73,42.66)
  BOTTOM w0.3: J17.16 7.37,30.45 5.07,28.15 5.07,13.35 11.57,6.85 59.16,6.85 72.62,20.31 72.62,39.55 v1(75.73,42.66)
N20028206: length 3.4
  TOP w0.3: R33.1 R37.1 72.93,38.17
N20031278: length 1.6
  TOP w0.2: U1.10 31.31,54.09 30.96,53.74 C15.1
N20031514: length 2.3
  TOP w0.2: C5.2 34.8,59.72 arc(34.77,59.59) 34.7,59.48 34.68,59.46 arc(34.55,59.27) 34.51,59.05 U1.31
  TOP w0.493: C5.2 L1.1
N20035363: length 2.4
  TOP w0.3: C26.1 40.86,9.94 R9.2 U2.4
N20050417: length 2.7
  TOP w0.2: J11.3 14.73,61.71 R15.1
N20050429: length 2.7
  TOP w0.2: R14.1 15.53,61.61 J11.2
N20122497: length 4.4
  TOP w0.2: 38.2,56.78 37.9,56.78 37.63,56.51 U1.24
  TOP w0.3: 38.2,56.78 39.1,56.78 39.33,57.01 L2.1
N20122505: length 4.3
  TOP w0.2: U1.22 37.97,55.71 38.31,55.37
  TOP w0.3: L3.1 39.58,54.1 38.31,55.37
N20122726: length 4.5
  TOP w0.2: U1.26 37.13,57.31 37.55,57.73 37.7,57.88 38,57.88
  TOP w0.3: 38,57.88 38.7,57.88 C13.1
N20123815: length 2.5
  TOP w0.3: U4.4 50.5,8.61 C29.1 R12.2
N20128470: length 12.3
  TOP w0.2: Q2.3 37.77,36.65 36.2,35.08 33.5,35.08 32.6,34.18 32.6,32.68 31.9,31.98 30.7,31.98 30.2,32.48 30.2,32.48 D4.C
N20128482: length 2.2
  TOP w0.2: R51.1 R47.2 41.44,35.64 Q2.1
N20128486: length 1.3
  TOP w0.2: R7.2 D4.A
N20128502: length 2.3
  TOP w0.2: Q3.3 31.39,36.84 D1.C
N20128524: length 2.3
  TOP w0.2: Q3.1 34.84,35.83 R48.1 R39.2
N20128528: length 1.3
  TOP w0.2: R4.2 D1.A
N20128530: length 11
  TOP w0.2: D3.C 30.46,30.58 36.7,30.58 38.03,31.91 Q4.3
N20128552: length 3.2
  TOP w0.2: R50.1 R46.2 41.13,33.41 40.21,32.49 Q4.1
N20128556: length 1.3
  TOP w0.2: R6.2 D3.A
N20128560: length 4
  TOP w0.2: Q5.3 31.41,34.07 30.28,35.2 D2.C
N20128580: length 3.3
  TOP w0.2: Q5.1 33.59,32.37 34.43,33.21 R45.2 35.01,33.22 R49.1
N20128584: length 1.3
  TOP w0.2: R5.2 D2.A
N20160217: length 3.7
  TOP w0.2: 34.51,53.18 U1.18
  TOP w0.3: C23.1 34.51,52.28 34.51,53.18
N20160455: length 4.6
  TOP w0.2: U1.12 32.11,53.69 31.81,53.39 31.81,52.84 31.46,52.49 31.12,52.49 C20.1
N20160512: length 5.4
  TOP w0.2: 31.71,54.76 31.71,53.79 31.46,53.54 31.46,52.99 31.32,52.84 30.27,52.84 C19.1
N20164995: length 3.7
  TOP w0.493: L4.2 34.8,65.63 C44.2 34.8,68.38 J1.1
N20165028: length 1.8
  TOP w0.493: L4.1 C6.2 L1.2
N20174575: length 10.7
  BOTTOM w0.3: 60.3,45.38 60.3,43.48 60.6,43.18 J16.6 ; 60.3,45.38 60.3,46.05 ; 60.3,45.38 60.64,45.72 ; J16.2 60.68,48.26 60.3,47.88 60.3,46.05 ; 60.3,46.05 60.64,45.72 ; 60.64,45.72 J16.4
N20174708: length 10.6
  BOTTOM w0.3: J16.18 63.6,27.94 63.9,28.24 63.9,30.18 ; 63.9,30.78 63.9,32.58 63.46,33.02 J16.14 ; 63.9,30.78 63.9,30.18 ; 63.9,30.78 63.6,30.48 ; 63.9,30.18 63.6,30.48 ; 63.6,30.48 J16.16

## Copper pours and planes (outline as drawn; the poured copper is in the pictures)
GND on TOP: 36.44,70.27 74.55,70.27 76.49,69.47 77.29,67.53 77.29,4.19 75.95,2.85 45.26,2.85 42.72,0.31 10.21,0.31 7.67,2.85 1,2.85 0.51,3.05 0.31,3.54 0.31,67.53 1.11,69.47 3.05,70.27 33.1,70.27 33.1,66.31 34.05,66.31 34.05,58.99 35.55,58.99 35.55,66.31 36.44,66.31 ; 47 cut-outs
GND on BOTTOM: 36.44,70.27 74.55,70.27 76.49,69.47 77.29,67.53 77.29,4.19 75.95,2.85 45.26,2.85 42.72,0.31 10.21,0.31 7.67,2.85 1,2.85 0.51,3.05 0.31,3.54 0.31,67.53 1.11,69.47 3.05,70.27 33.1,70.27 33.1,66.31 36.44,66.31 ; 29 cut-outs
GND on GND: 36.44,70.27 74.55,70.27 76.49,69.47 77.29,67.53 77.29,4.19 75.95,2.85 45.26,2.85 42.72,0.31 10.21,0.31 7.67,2.85 1,2.85 0.51,3.05 0.31,3.54 0.31,67.53 1.11,69.47 3.05,70.27 33.1,70.27 33.1,66.31 36.44,66.31
VBUS on POWER: 17.9,66.87 27,66.87 27.11,66.76 27.11,63.71 27.07,63.64 27.09,61.68 27.3,61.68 29.6,59.38 42.4,59.38 43.57,60.55 70.9,60.58 70.95,47.78 70.91,47.71 70.9,47.62 70.91,47.54 70.95,47.47 70.96,46.81 70.96,45.58 70.76,45.78 65.96,45.78 65.95,57.15 65.88,57.33 65.7,57.4 62.7,57.4 62.69,57.4 34.36,57.36 34.36,55.18 33.2,54.02 33.2,53.38 21.96,53.38 18,57.34 18,60.83 17.93,61.01 17.75,61.08 17.75,61.08 9.59,61.02 9.61,63.44 15.81,63.44 15.99,63.51 16.06,63.69 16.06,64.88 16.16,64.78 17.9,64.78
EXT_3V3 on POWER: outline of 99 points within 0.3,29.08 77.3,70.28 ; 1 cut-out
LEVEL_SHIFT on POWER: 9.72,60.52 17.45,60.58 17.45,57.08 23.15,51.38 33.75,51.38 33.95,51.18 33.94,48.63 33.94,48.58 33.94,44.22 33.96,44.12 34.01,44.04 35.71,42.34 36.88,41.14 36.87,38.33 36.86,38.28 36.85,38.23 36.83,29.27 27.45,29.27 27.45,39.52 27.43,39.61 27.38,39.69 14.07,53 14.07,53.02 14.07,53.07 14.05,53.12 14.06,57.24 14.07,57.29 14.08,57.34 14.07,57.39 14.06,57.45 13.97,57.6 13.81,57.65 9.93,57.65 9.89,57.65 9.86,57.64 9.61,57.89 9.61,60.41
TL_AVDD3 on POWER: 40.05,56.48 40.05,55.64 40.07,55.54 40.12,55.46 40.13,55.45 40.21,55.4 40.31,55.38 42.42,55.38 42.42,48.54 42.44,48.45 42.49,48.37 42.52,48.34 42.6,48.28 42.7,48.26 51.56,48.26 52.76,47.07 52.84,47.01 52.93,46.99 59,46.99 59,43.54 59.06,43.48 59.06,36.95 55.27,36.95 55.2,36.88 55.2,29.48 54.7,28.98 52.67,28.98 52.64,28.95 43.32,29.01 43.26,29.07 43.23,41.09 43.3,41.09 43.3,45.79 40.49,45.79 40.4,45.88 40.4,53.37 39.9,53.87 37.94,55.44 37.86,55.48 37.78,55.49 35,55.49 35,56.48
TL_FVDD2V on POWER: 62.8,56.9 65.45,56.9 65.47,39.62 62.5,39.62 62.5,29.79 62.17,29.46 58.44,29.46 58.35,29.44 58.27,29.4 57.1,29.4 57.1,30.88 59.25,30.88 59.27,30.91 61.23,30.91 61.6,31.28 61.6,41.72 63.3,41.72 63.48,41.8 63.55,41.97 63.56,55.63 63.49,55.8 63.31,55.88 46,55.88 45.7,56.18 45.7,56.88
TL_VBAT on POWER: 37.05,52.33 38.2,52.33 38.55,50.75 38.51,48.52 38.51,48.47 38.52,48.43 39.93,44.31 39.99,44.21 40.09,44.15 42.71,41.24 42.71,29.02 42.72,28.94 42.76,28.87 42.76,28.76 42.83,28.59 43.01,28.52 43.04,28.52 43.04,16.63 3.48,16.63 3.49,29 3.49,30.67 3.49,42.1 4.36,42.1 4.44,42.06 4.53,42.04 4.65,42.06 4.73,42.1 6.82,42.1 6.88,42.04 6.95,41.99 7.08,24.57 7.09,24.38 7.09,24.13 7.16,23.95 7.34,23.88 7.35,23.88 39.9,23.94 40.08,24.02 40.15,24.19 40.15,24.2 40.1,29.07 40.1,41.34 40.09,41.42 40.05,41.49 36.98,45.36 37.01,48.77
TL_VDD1V2_O on POWER: 53.75,52.48 53.75,49.69 53.74,49.64 53.73,49.59 53.75,49.5 53.8,49.42 53.93,49.29 54.01,49.24 54.11,49.22 57.73,49.22 57.73,47.49 53.04,47.49 51.84,48.69 51.76,48.74 51.66,48.76 42.92,48.76 42.92,52.48
TL_VDD2V_O on POWER: 44,55.38 63.06,55.38 63.05,42.22 60.9,42.22 60.9,33.23 60.25,32.58 56.7,32.58 56.7,33.86 56.75,33.91 56.93,33.99 57,34.16 56.99,34.22 56.97,34.28 56.97,36.45 59.31,36.45 59.49,36.53 59.56,36.7 59.56,43.37 59.6,43.37 59.6,47.49 58.23,47.49 58.23,49.47 58.16,49.64 57.98,49.72 54.25,49.72 54.25,52.64 54.23,52.74 54.18,52.82 53.67,53.33 53.59,53.38 53.49,53.4 44,53.4
TL_VDDO3 on POWER: outline of 86 points within 0.3,0.3 77.3,63.06 ; 1 cut-out

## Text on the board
Ref Des/Silkscreen Bottom: GND | VBAT | SHIFT | VBUS | VCOM | VDDO3 | NC | EXT_3V3 | SWS | VADJ | VDW | VUP | VDD25EF | USBVBUS | AVDD3 | VDD2V_O | VDD2CDC | DVDD1V2 | VDD1V2_O | RFVDD1V2 | FVDD2V | 2V | 1V2 | 2023-09-13 | C1T307A20_V1.2 | 7628-40ohm
User.Comments: RESET | IOREF | 3V3 | 5V | TX | RX | # | SCL | AREF | GND | 13 | 12 | 11 | 10 | 9 | 8 | 7 | 6 | 5 | 4 | 3 | 2 | 1 | 0 | SDA | A0 | A5 | VIN | A2 | A1 | A4 | A3 | [#=PWM] | www.arduino.cc | UNO_Rev3.01 | #4 | #5 | #3 | #1 | #2 | TOP | BOTTOM | POWER | ANALOG IN | L | ON | DIGITAL | R10 | R9 | ESD1 | D1 | X1 | E1 | E2 | C3 | C4 | C5 | Cp1 | U2 | ZU4 | C12 | C2 | U1 | R2 | R1 | R3 | R8 | U5' | U5 | C8 | C10 | D2 | F1 | C1 | T1 | R6 | U3 | R14 | R15 | ICSP | R13 | Y2 | R12 | R7 | C11 | C9 | R4 | RESET-EN | R11 | C6 | L1 | X2 | C7 | Y1 | IOL | IOH | GROUND | Xduino
Ref Des/Silkscreen Top: TL_MICBIAS | PA3 | DP | GND | PA2 | PA4 | DM | AORN | AOLP | AORP | MICR | AOLN | MICL | DMICCK1 | PA7 | PA6 | DMICCK2 | DMICDAT | PA5 | MICBIAS | MICR1 | MICL1 | AOLN1 | AORN1 | AOLP1 | AORP1 | SPK-R | K1 | K3 | SPK-L | K2 | K4 | PE7 | PB2 | PF0 | PB0 | PF1 | PF2 | PB1 | RESET | LEDR | LEDG | LEDB | LEDW | KEY1 | KEY4 | KEY3 | KEY2 | 3.3V|1.8V | MIC-R | MIC-L
DISPLAY_TOP: FIGURE | FINISHED_SIZE | 0.3 | 0.889 | 0.9 | 1.0 | DRILL CHART: TOP to BOTTOM | ALL UNITS ARE IN MILLIMETERS | PLATED | NON-PLATED | QTY | 688 | 1 | 5 | 12 | 8 | 2
